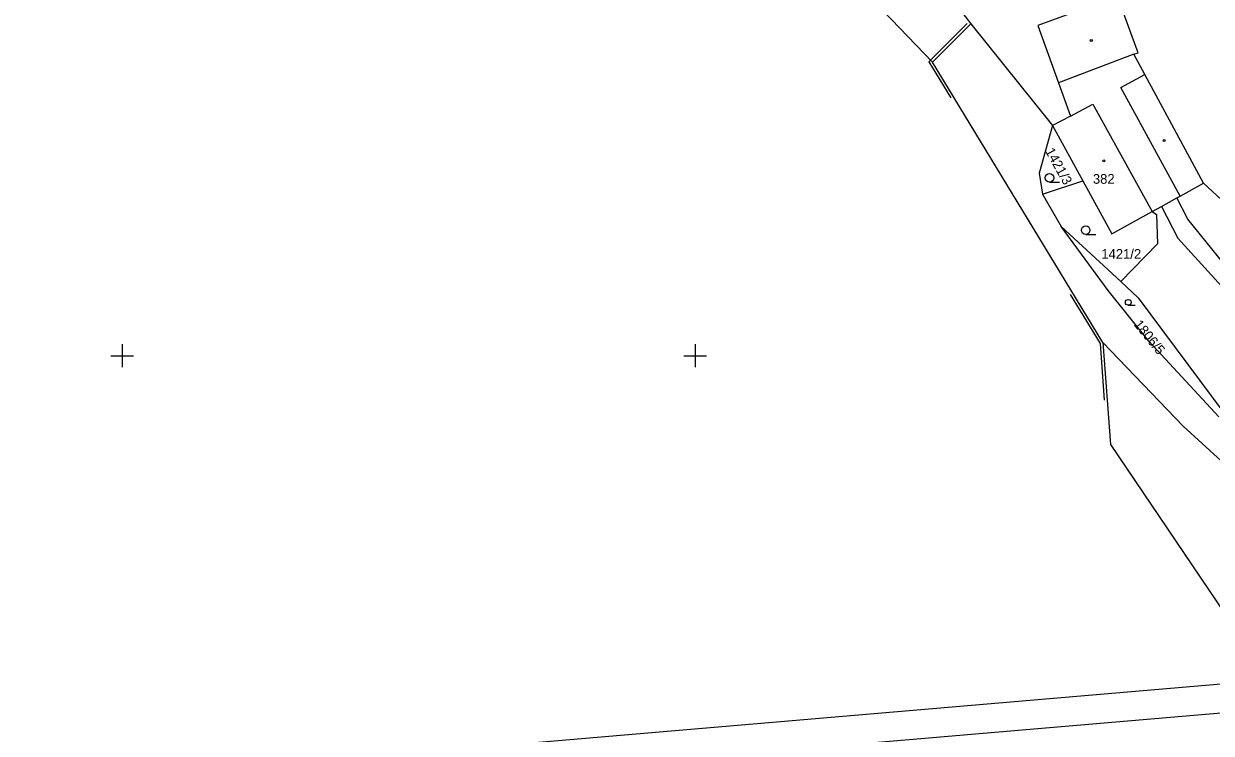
# Model space of a CAD drawing. Extents: x -779302 to -774398, y -1144902 to -1142831.
# Drawn here: x -778617.2 to -778409.9, y -1143565.9 to -1143442 of the extents above; entities that cross this region are included whole.
import ezdxf

# ---------------------------------------------------------------- set-up
doc = ezdxf.new("R2010")
doc.units = 0
for name, color, linetype in [('hektosit - Vrstva 5', 7, 'Continuous'), ('Hranice parcel', 7, 'Continuous'), ('Parcelní čísla', 7, 'Continuous'), ('Vnitřní kresba', 7, 'Continuous'), ('Vrstva 1', 7, 'Continuous'), ('Značky budov', 7, 'Continuous'), ('Značky kultur', 7, 'Continuous')]:
    doc.layers.add(name, color=color, linetype=linetype)

msp = doc.modelspace()

# ---------------------------------------------------------------- linework, layer by layer
at = {"layer": 'hektosit - Vrstva 5'}
for p, q in [((-778600, -1143498), (-778600, -1143502)), ((-778500, -1143498), (-778500, -1143502)), ((-778602, -1143500), (-778598, -1143500)), ((-778502, -1143500), (-778498, -1143500))]:
    msp.add_line(p, q, dxfattribs=at)
at = {"layer": 'Hranice parcel'}
for p, q in [((-778465.13, -1143424.95), (-778451.86, -1143442.04)), ((-778458.56, -1143448.73), (-778468.65, -1143438.25)), ((-778458.56, -1143448.73), (-778451.86, -1143442.04)), ((-778451.86, -1143442.04), (-778437.65, -1143459.82)), ((-778428.85, -1143497.7), (-778458.56, -1143448.73)), ((-778437.65, -1143459.82), (-778432.35, -1143469.46)), ((-778439.35, -1143471.76), (-778432.35, -1143469.46)), ((-778439.35, -1143471.76), (-778436.1, -1143477.46)), ((-778418.6, -1143473.93), (-778415.92, -1143472.44)), ((-778420.24, -1143474.84), (-778418.6, -1143473.93)), ((-778436.1, -1143477.46), (-778425.71, -1143487.05)), ((-778427.89, -1143488.63), (-778436.1, -1143477.46)), ((-778419.29, -1143480.44), (-778425.71, -1143487.05))]:
    msp.add_line(p, q, dxfattribs=at)
for points in [[(-778411.25, -1143469.85), (-778421.51, -1143450.89), (-778423.42, -1143447.36), (-778422.68, -1143447.08), (-778426.28, -1143437.21), (-778440.22, -1143442.3), (-778436.59, -1143452.33), (-778434.47, -1143458.19), (-778437.65, -1143459.82)], [(-778437.65, -1143459.82), (-778439.93, -1143468.1), (-778439.35, -1143471.76)], [(-778432.35, -1143469.46), (-778427.25, -1143478.73), (-778420.24, -1143474.84)], [(-778415.92, -1143472.44), (-778415.35, -1143472.13), (-778411.25, -1143469.85)], [(-778411.25, -1143469.85), (-778384.6, -1143494.61), (-778377.84, -1143512.85)], [(-778377.84, -1143512.85), (-778393.35, -1143498.23), (-778407.6, -1143484.07), (-778414.02, -1143476.15), (-778415.92, -1143472.44)], [(-778420.24, -1143474.84), (-778419.49, -1143475.35), (-778419.29, -1143480.44)], [(-778418.6, -1143473.93), (-778415.77, -1143479.46), (-778396.37, -1143500.75), (-778379.92, -1143515.38), (-778374.08, -1143521.03), (-778355.81, -1143536.2), (-778338.03, -1143555.79)], [(-778425.71, -1143487.05), (-778422.69, -1143489.91), (-778403.28, -1143515.89)], [(-778408.6, -1143510.68), (-778420.83, -1143497.44), (-778427.89, -1143488.63)], [(-778273.31, -1143597.02), (-778277.63, -1143592.38), (-778304.71, -1143577.98), (-778330.53, -1143563.4), (-778390.82, -1143530.99), (-778402.19, -1143523.83), (-778414.83, -1143512.31), (-778428.85, -1143497.7)], [(-778428.85, -1143497.7), (-778427.52, -1143515.51), (-778391.96, -1143568.16), (-778391.52, -1143569.91)]]:
    msp.add_lwpolyline(points, dxfattribs=at)
at = {"layer": 'Vnitřní kresba'}
for p, q in [((-778459.19, -1143448.66), (-778452.52, -1143442)), ((-778423.42, -1143447.36), (-778436.59, -1143452.33)), ((-778459.19, -1143448.66), (-778455.37, -1143454.96)), ((-778425.7, -1143453.15), (-778421.51, -1143450.89)), ((-778415.35, -1143472.13), (-778425.7, -1143453.15)), ((-778434.47, -1143458.19), (-778430.62, -1143456.06)), ((-778430.62, -1143456.06), (-778420.24, -1143474.84)), ((-778434.53, -1143489.3), (-778429.34, -1143497.86)), ((-778429.34, -1143497.86), (-778428.6, -1143507.77))]:
    msp.add_line(p, q, dxfattribs=at)
at = {"layer": 'Vrstva 1'}
for points in [[(-777571, -1143485.76), (-778617.18, -1143575.21), (-778591.88, -1143871.12), (-777545.7, -1143781.67)], [(-777551.11, -1143777.12), (-778587.32, -1143865.71), (-778611.77, -1143579.77), (-777575.56, -1143491.17)]]:
    msp.add_lwpolyline(points, close=True, dxfattribs=at)
at = {"layer": 'Značky budov'}
for centre in [(-778430.86, -1143444.93), (-778418.15, -1143462.42), (-778428.68, -1143465.98)]:
    msp.add_circle(centre, 0.175, dxfattribs=at)
at = {"layer": 'Značky kultur'}
for p, q in [((-778438.17, -1143469.68), (-778436.42, -1143469.68)), ((-778431.84, -1143478.81), (-778430.09, -1143478.81)), ((-778424.4, -1143491.18), (-778423.22, -1143491.18))]:
    msp.add_line(p, q, dxfattribs=at)
for centre, radius in [((-778438.17, -1143468.93), 0.75), ((-778431.84, -1143478.06), 0.75), ((-778424.4, -1143490.68), 0.502)]:
    msp.add_circle(centre, radius, dxfattribs=at)

# ---------------------------------------------------------------- texts
at = {"layer": 'Parcelní čísla'}
for s, rotation, p in [('1421/3', 299, (-778438.96, -1143464.26)), ('1806/5', 309, (-778423.54, -1143494.58))]:
    msp.add_text(s, height=1.7, rotation=rotation, dxfattribs=at).set_placement(p)
for s, p in [('382', (-778430.58, -1143469.97)), ('1421/2', (-778429.11, -1143483.07))]:
    msp.add_text(s, height=1.7, dxfattribs=at).set_placement(p)

doc.saveas('drawing.dxf')
